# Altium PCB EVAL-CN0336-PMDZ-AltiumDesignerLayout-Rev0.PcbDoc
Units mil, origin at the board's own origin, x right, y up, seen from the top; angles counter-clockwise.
Board outline 2055 x 800 mil, 2 copper layers (Top Layer, Bottom Layer); 30 components, 22 nets, 95 pads, 26 vias.
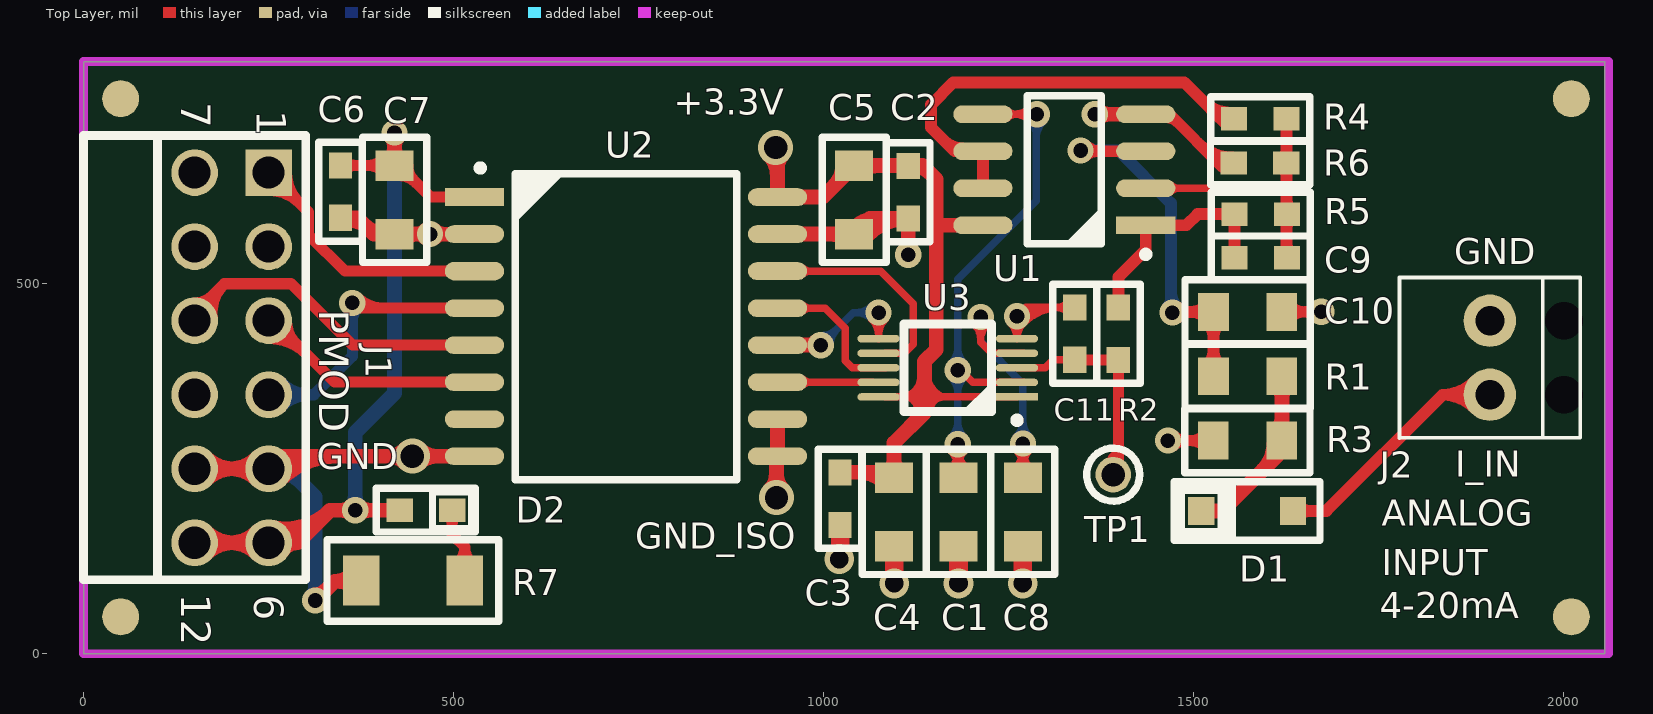
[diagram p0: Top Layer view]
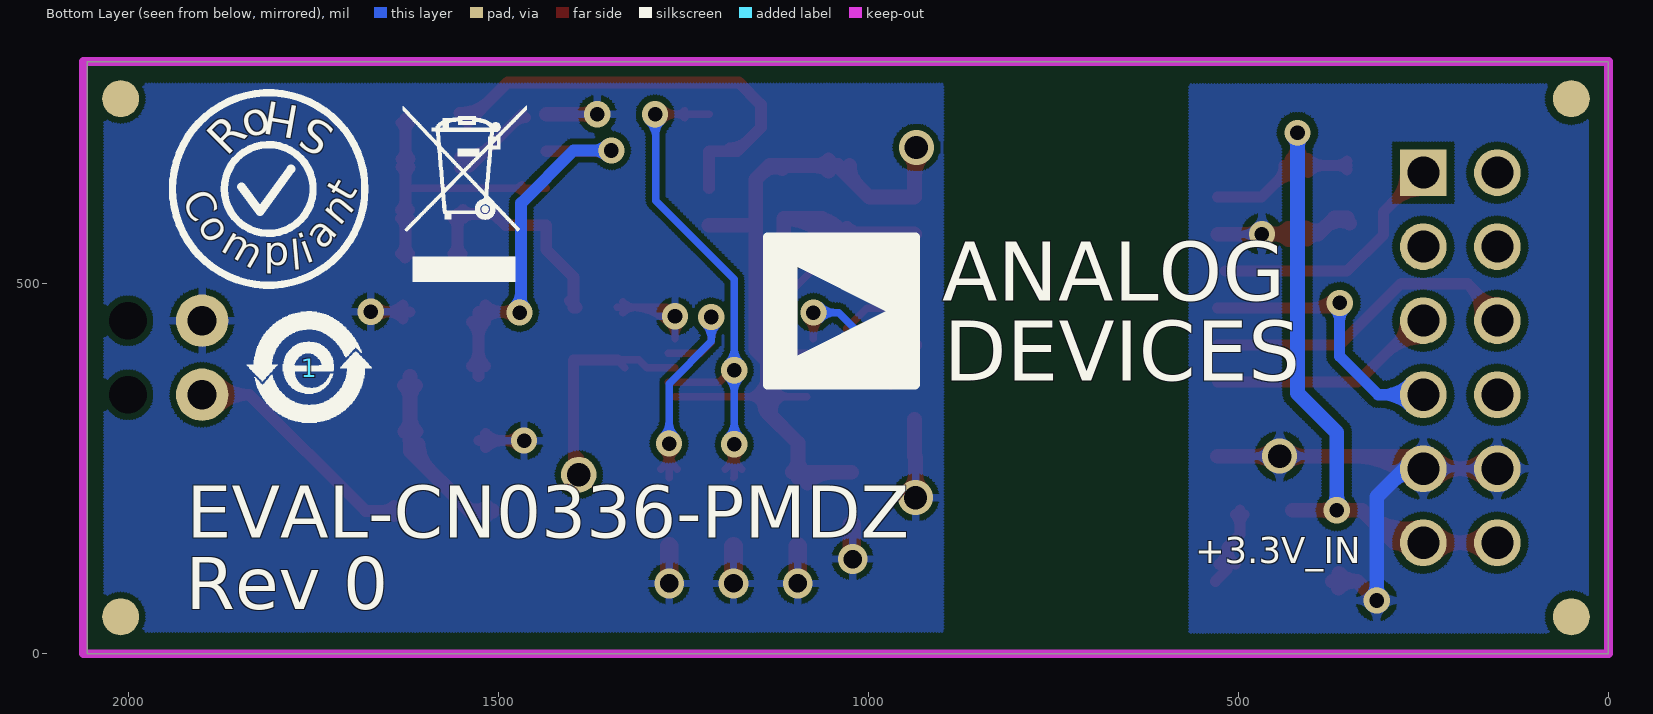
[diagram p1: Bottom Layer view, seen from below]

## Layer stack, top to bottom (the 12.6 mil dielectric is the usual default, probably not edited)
Top Layer: signal copper 1.4
Dielectric: dielectric 12.6, FR-4, Dk 4.8
Bottom Layer: signal copper 1.4

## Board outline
0,0 2055,0 2055,800 0,800

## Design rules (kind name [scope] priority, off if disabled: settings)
Clearance [All] p1: gap=8
ComponentClearance [All] p1 off: gap=10 collisioncheckmode=3 verticalgap=10 showdistances=FALSE
PolygonConnect [All] p1: connectstyle=Relief reliefconductorwidth=10 reliefentries=4 polygonreliefangle="90 Angle"
RoutingVias [All] p1: holewidth=19.68 width=35.43 viastyle="Through Hole" minholewidth=19.68 minwidth=35.43 maxholewidth=39.37 maxwidth=78.74
SilkscreenOverComponentPads [All] p1: minsilkscreentomaskgap=10
SolderMaskExpansion [All] p1: expansion=4
Width [All] p1: maxlimit=60 minlimit=10 preferedwidth=10
26 further rules are at their usual default settings.

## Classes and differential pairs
component class CN0336: C1 C2 C3 C4 C5 C6 C7 C8 C9 C10 C11 D1 D2 J1 J2 R1 R2 R3 R4 R5 R6 R7 U1 U2 U3

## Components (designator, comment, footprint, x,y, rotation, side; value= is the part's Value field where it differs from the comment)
1 "Comment" "Sign E" 1755,386 r180 bottom
C1 "" "0805 AD" 1182,238 r270 top
C2 "" "0603 AD" 1114,588 r90 top
C3 "" "0603 AD" 1022,245 r270 top
C4 "" "0805 AD" 1095,238 r270 top
C5 "Cap" "0805 AD" 1041,567 r90 top
C6 "" "0603 AD" 347,589 r90 top
C7 "Cap" "0805 AD" 420,567 r90 top
C8 "" "0805 AD" 1269,238 r270 top (schematic designator C12)
C9 "" "0603 AD" 1555,535 r0 top
C10 "" "0805 AD" 1619,462 r180 top
C11 "" "0603 AD" 1339,468 r270 top (schematic designator C9)
D1 "" SOD123 1572,193 r180 top
D2 "LED3" "0603 Diode" 427,194 r0 top (schematic designator D1)
J1 "PMOD CON 12 Pin" "PMOD 12 Pin" 200,400 r270 top locked
J2 "CON 2" "Phoenix Klema pitch 2_54" 1900,350 r90 top
R1 "RESISTOR" "0805 AD" 1619,375 r180 top
R2 "RESISTOR" "0603 AD" 1398,397.08 r90 top (schematic designator R3)
R3 "RESISTOR" "0805 AD" 1526,288 r0 top
R4 "RESISTOR" "0603 AD" 1625,723 r180 top
R5 "RESISTOR" "0603 AD" 1555,594 r0 top
R6 "RESISTOR" "0603 AD" 1554,663 r0 top
R7 "RESISTOR" "1206 AD" 375,99 r0 top
TP1 "Comment" TestPoint 1391,242 r0 top
U1 "AD8606" SOICN_8 1435,579 r180 top
U2 "ADuM5401" SOICW_16 528,617 r0 top
U3 "AD7091R" MSOP10 1261,347 r90 top
? "Comment" "ROHS COMPLIANT" 1810,628 r180 bottom
? "Comment" "Analog Devices" 1136,363 r180 bottom
? "Comment" "No Trash" 1547,610 r180 bottom

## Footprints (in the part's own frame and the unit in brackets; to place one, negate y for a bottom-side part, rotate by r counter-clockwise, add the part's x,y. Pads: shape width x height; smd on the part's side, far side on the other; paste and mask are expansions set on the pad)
"0603 AD" [mm]
  rect 0.9x0.8 smd: 1(0,0) 2(1.8,0)
  silkscreen extent -0.8,-0.75 2.6,0.75
"0603 Diode" [mm]
  rect 0.9x0.8 smd: A(0,0) K(1.8,0)
  silkscreen extent -0.8,-0.75 2.6,0.76
"0805 AD" [mm]
  rect 1.05x1.3 smd: 1(0,0) 2(2.35,0)
  silkscreen extent -0.98,-1.1 3.32,1.1
"1206 AD" [mm]
  rect 1.25x1.7 smd: 1(0,0) 2(3.55,0)
  silkscreen extent -1.17,-1.4 4.72,1.4
"Analog Devices" [mil]
  silkscreen extent -1,0 201,201
MSOP10 [mm]
  rect 0.254x1.45 smd: 1(0,0)
  oval 0.254x1.45 smd: 2(0.5,0) 3(1,0) 4(1.5,0) 5(2,0) 6(2,4.75) 7(1.5,4.75) 8(1,4.75) 9(0.5,4.75) 10(0,4.75)
  silkscreen extent -0.88,-0.08 2.5,3.87
"No Trash" [mil]
  silkscreen extent -82,-107 86,130
"Phoenix Klema pitch 2_54" [mm]
  round 1.8 hole 1: 1(0,0) 2(2.54,0)
  round 0 hole 1.3: ""(0,-2.54) ""(2.54,-2.54)
  silkscreen extent -1.48,-3.1 4.02,3.1
"PMOD 12 Pin" [mm]
  rect 1.6x1.6 hole 1.1: 1(-6.35,1.27)
  round 1.6 hole 1.1: 2(-3.81,1.27) 3(-1.27,1.27) 4(1.27,1.27) 5(3.81,1.27) 6(6.35,1.27) 7(-6.35,-1.27) 8(-3.81,-1.27) 9(-1.27,-1.27) 10(1.27,-1.27) 11(3.81,-1.27) 12(6.35,-1.27)
  silkscreen extent -7.62,-5.08 7.62,2.54
"ROHS COMPLIANT" [mil]
  silkscreen extent -130,-130 130,130
"Sign E" [mil]
  silkscreen extent -85,-74 84,76
SOD123 [mm]
  rect 0.9x0.95 smd: A(-1.575,0) K(1.575,0)
  silkscreen extent -2.5,-1 2.5,1
SOICN_8 [mil]
  rect 80x24 smd: 1(0,0)
  oval 80x24 smd: 2(0,-50) 3(0,-100) 4(0,-150) 5(220,-150) 6(220,-100) 7(220,-50) 8(220,0)
  silkscreen extent -3,-175 160,43
SOICW_16 [mil]
  rect 80x24 smd: 1(0,0)
  oval 80x24 smd: 2(0,-50) 4(0,-150) 5(0,-200) 6(0,-250) 7(0,-300) 8(0,-350) 9(409.45,-350) 10(409.45,-300) 11(409.45,-250) 12(409.45,-200) 13(409.45,-150) 14(409.45,-100) 15(409.45,-50) 16(409.45,0)
  oval 80x25 smd: 3(0,-100)
  silkscreen extent 5,-382 354,43
TestPoint [mil]
  round 48 hole 32: 1(0,0)
  silkscreen extent -36,-36 36,36

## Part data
C1 C2 C3 C4 C6 C8 C9 C10 C11: library part Cap, "Capacitor"
C5 C7: "Capacitor"
D1: library part Diode, "Diode"
D2: "LED"
J1: "PMOD CONNECTOR 12 PIN"
J2: "Input Connector"
R1 R2 R3 R4 R5 R6 R7: "Resistor"
U1: "Dual Operational Amplifier"
U2: "Quad Digital Isolator with integrated DC/DC converter"
U3: "ADC"

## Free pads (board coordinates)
  round 50 all layers, no hole paste+15 mask+15: ""(50,50) ""(50,750) ""(2010,50) ""(2010,750)

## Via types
v1: diameter 35.43, hole 19.68, Top Layer to Bottom Layer, tented both sides, 18 vias
v2: diameter 40, hole 25, Top Layer to Bottom Layer, tented both sides, 4 vias
v3: diameter 47.24, hole 31.5, Top Layer to Bottom Layer, 3 vias
v4: diameter 35, hole 20, Top Layer to Bottom Layer, 1 vias

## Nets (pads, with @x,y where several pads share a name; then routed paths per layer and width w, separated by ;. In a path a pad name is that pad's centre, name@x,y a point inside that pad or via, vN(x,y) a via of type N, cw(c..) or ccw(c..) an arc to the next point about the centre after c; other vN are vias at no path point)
+3.3V: C2.2 C3.1 C4.1 C5.2 U1.8 U2.16 U3.1 U3.10 | length 1472.6
  Top Layer w10: C3.1@1021,244 C3.1 ; U3.10@1082.99,347 1136,347 U3.1 ; C4.1 C4.1@1102,245 ; 1107,347 ccw(c1103,375) 1131,379 ; 1111.14,347.72 cw(c1107.5,328.5) 1127,327 ; C2.2@1113.35,659.52 C2.2 ; 1130.29,320.29 ccw(c1132.29,332) 1144,330 cw(c1161.5,329.5) 1162,347 ; 1142.21,401.21 ccw(c1178.21,383) 1160,347
  Top Layer w19.68: C3.1 1088,245 C4.1 ; 1047.04,245 cw(c1047.04,194.96) C4.1@1082.42,230.34
  Top Layer w20: v3@925.37,674.37 cw(c896.2,645.2) 937.45,645.2 ; 937.45,657.03 cw(c961.97,657.03) v3@944.63,674.37 ; v3@937.45,681.55 U2.16 998.48,617 C5.2 1113.35,659.52 1133.48,659.52 1152,641 1152,579 ; 1014.39,632.91 ccw(c987.77,659.52) C5.2@1025.41,659.52 ; C5.2@1053.47,651.98 cw(c1071.68,633.76) 1071.68,659.52 cw(c1071.68,685.28) C5.2@1053.47,667.06 ; C4.1@1087.46,245.54 ccw(c1069.24,263.76) 1095,263.76 ccw(c1120.76,263.76) C4.1@1102.54,245.54 ; C4.1 1095,285 1136,326 1136,347 1136,395 1152,411 1152,579 ; C2.2@1116.25,655.54 cw(c1125.62,633.5) 1142.56,650.44 ; U1.8 1152,579
  other v3: 935,684
+3.3V_IN: C6.2 C7.2 D2.A J1.6 J1.12 U2.1 | length 1740.3
  Top Layer w15: C6.2@352.83,654.03 cw(c366.91,639.95) 366.91,659.87 cw(c366.91,679.78) C6.2@352.83,665.7 ; C6.2@353,659.87 420,659.87 425.65,659.87 468.52,617 U2.1 ; 382.45,659.87 cw(c382.45,626.89) C7.2@405.77,650.21 ; 384.12,659.87 ccw(c384.12,690.48) C7.2@405.77,668.83 ; C7.2@424.92,646.35 cw(c424.92,611.95) 449.24,636.28 ; C7.2@438.09,659.52 ccw(c467.28,659.52) 446.64,638.88
  Top Layer w20: J1.12 J1.6 289,150 ; J1.12@165.2,134.8 cw(c201.9,98.1) 201.9,150 cw(c201.9,201.9) J1.12@165.2,165.2 ; J1.6@234.8,134.8 ccw(c198.1,98.1) 198.1,150 ccw(c198.1,201.9) J1.6@234.8,165.2 ; J1.6@250.32,151.46 ccw(c263.48,211.76) 307.12,168.12 ; J1.6@254.58,171 ccw(c272.75,254.25) 333,194 ; J1.6@268.18,138.52 cw(c289,125.37) 289,150 ; J1.6@268.18,161.48 ccw(c289,174.63) 289,150 ; v1@361.54,188.54 ccw(c348.37,175.37) 348.37,194 ccw(c348.37,212.63) v1@361.54,199.46 ; v1@372.46,188.54 cw(c385.63,175.37) 385.63,194 cw(c385.63,212.63) v1@372.46,199.46 ; C7.2@412.46,667.06 ccw(c394.24,685.28) 420,685.28 ccw(c445.76,685.28) C7.2@427.54,667.06 ; v4@414.7,698.7 cw(c401.89,685.89) 420,685.89 cw(c438.11,685.89) v4@425.3,698.7 ; C7.2 420,659.87 v4(420,704) ; D2.A v1(367,194) 333,194 ; 289,150 333,194
  Bottom Layer w20: v1@361.54,199.46 ccw(c348.37,212.63) 367,212.63 ccw(c385.63,212.63) v1@372.46,199.46 ; v1(367,194) 367,299 420,352 v4(420,704) ; v4@414.7,698.7 cw(c401.89,685.89) 420,685.89 cw(c438.11,685.89) v4@425.3,698.7
GND: C6.1 C7.1 J1.5 J1.11 R7.1 U2.2 U2.8 | length 1619.7
  Top Layer w19.68: v1(313,72) 339,98 ; v1@313,79.87 ccw(c313,98.88) 326.44,85.44 ccw(c339.88,72) v1@320.87,72 ; 341.77,98 cw(c341.77,65.77) R7.1@364.56,88.56 ; C6.1@349.67,581.76 cw(c362.45,556.49) 382.48,576.52 ; C6.1@353,589 370,589 392,567 ; R7.1@364.15,109.01 cw(c339,132.22) 339,98 ; R7.1@373,98 339,98 ; 381.54,577.46 ccw(c396.09,592.01) C7.1@408.53,575.62 ; C7.1@406.75,560.08 ccw(c392,547.82) 392,567 ; C7.1@406.75,573.92 cw(c392,586.18) 392,567 ; C7.1@432.58,559.34 cw(c451.06,540.86) 451.06,567 cw(c451.06,593.14) C7.1@432.58,574.66 ; v1@462.43,561.43 ccw(c448.99,547.99) 448.99,567 ccw(c448.99,586.01) v1@462.43,572.57 ; v1@473.57,561.43 cw(c487.01,547.99) 487.01,567 cw(c487.01,586.01) v1@473.57,572.57 ; U2.2 392,567
  Top Layer w20: J1.11 J1.5 267,267 U2.8 ; J1.11@165.2,234.8 cw(c201.9,198.1) 201.9,250 cw(c201.9,301.9) J1.11@165.2,265.2 ; J1.5@234.8,234.8 ccw(c198.1,198.1) 198.1,250 ccw(c198.1,301.9) J1.5@234.8,265.2 ; J1.5@251.06,248.94 cw(c294.65,205.35) 294.65,267 ; J1.5@265.2,234.8 cw(c342.94,157.06) 342.94,267 ; v3@434.37,257.37 ccw(c411.11,234.11) 411.11,267 ccw(c411.11,299.89) v3@434.37,276.63 ; v3@453.63,257.37 cw(c476.89,234.11) 476.89,267 cw(c476.89,299.89) v3@453.63,276.63
  Bottom Layer w20: J1.5 275,250 313,212 v1(313,72) ; J1.5@250.06,248.51 cw(c252.55,190.88) 293.33,231.67 ; v1@307.54,77.46 ccw(c294.37,90.63) 313,90.63 ccw(c331.63,90.63) v1@318.46,77.46
  other v1: 468,567
  other v3: 444,267
GND_ISO: C1.2 C2.1 C3.2 C4.2 C5.1 C8.2 C10.1 C11.1 J2.2 R3.1 R6.1 U1.4 U2.9 U2.10 U2.15 U3.5 | length 1659.4
  Top Layer w10: v1@1252.1,446.92 cw(c1231.36,425.74) U3.5 ; v1@1262.92,454.08 cw(c1296.53,420.47) 1296.53,468 ; v1@1269.9,446.92 ccw(c1290.64,425.74) U3.5 ; v1@1269.99,447.01 cw(c1320.67,396.33) 1320.67,468 ; v1@1270,462 v1(1261,456) ; C11.1@1331.4,460.4 ccw(c1313.05,442.05) 1313.05,468 ccw(c1313.05,493.95) C11.1@1331.4,475.6 ; C11.1 1273,468 v1(1261,456) ; U3.5 v1(1261,456)
  Top Layer w15: U1.4@1463,724.5 cw(c1463,703.98) 1477.51,718.49 ; U1.4@1467,729 R6.1@1538,658 ; v1@1472.22,280.78 cw(c1489.66,263.34) 1489.66,288 cw(c1489.66,312.66) v1@1472.22,295.22 ; v1@1478,288 R3.1 ; 1505.46,690.54 ccw(c1552.03,737.11) R6.1@1552.03,671.25 ; R3.1@1516.69,278.69 ccw(c1494.21,256.21) 1494.21,288 ccw(c1494.21,319.79) R3.1@1516.69,297.31 ; 1531.07,664.93 ccw(c1552.03,685.89) R6.1@1552.03,656.25 ; C10.1 v1(1672,462) ; C10.1@1628.31,452.69 cw(c1650.79,430.21) 1650.79,462 cw(c1650.79,493.79) C10.1@1628.31,471.31 ; v1@1664.78,454.78 ccw(c1647.34,437.34) 1647.34,462 ccw(c1647.34,486.66) v1@1664.78,469.22
  Top Layer w20: v3@926.37,220.63 ccw(c903.11,243.89) 936,243.89 ccw(c968.89,243.89) v3@945.63,220.63 ; v3(936,211) 936,265.55 U2.9 U2.10 ; U2.15 C5.1 1062,588 ; C5.1@1028.53,559.46 ccw(c1010.32,541.24) 1010.32,567 ccw(c1010.32,592.76) C5.1@1028.53,574.54 ; C5.1@1038.78,573.01 cw(c1071,545.88) 1071,588 ; C5.1@1054.08,560.13 cw(c1114,509.67) C2.1 ; C5.1@1056.37,569.17 cw(c1076.63,573.37) 1062,588 ; v1@1108.54,544.46 ccw(c1095.37,557.63) 1114,557.63 ccw(c1132.63,557.63) v1@1119.46,544.46 ; v1(1114,539) C2.1 ; v1(1366,729) U1.4 ; v1@1371.46,723.54 cw(c1384.63,710.37) 1384.63,729 cw(c1384.63,747.63) v1@1371.46,734.46 ; 1062,588 C2.1
  Top Layer w25: v2(1021,128) 1021,131 1022,132 C3.2 ; v2(1095,95) C4.2 ; v2(1182,95) C1.2 ; v2(1269,95) C8.2
  other v1: 1465,288
NetC1_1: C1.1 U1.5 U3.2 | length 1081.4
  Top Layer w10: C1.1@1170.92,249.08 ccw(c1146.59,273.41) v1@1181,273.41 ; v1@1172.01,274.01 cw(c1150.3,252.3) 1181,252.3 cw(c1211.7,252.3) v1@1189.99,274.01 ; v1@1181,278.24 ccw(c1222.24,278.24) C1.1@1193.08,249.08 ; v1(1181,283) 1181,239 C1.1 ; v1@1185,383 1201.31,366.69 U3.2 U3.2@1270,366.69 ; U1.5 v1(1288,729) ; U1.5@1247.95,724.05 cw(c1259.9,712.1) 1259.9,729 cw(c1259.9,745.9) U1.5@1247.95,733.95 ; v1@1279.01,720.01 ccw(c1257.3,698.3) 1257.3,729 ccw(c1257.3,759.7) v1@1279.01,737.99
  Bottom Layer w10: v1@1172.01,291.99 ccw(c1150.3,313.7) 1181,313.7 ccw(c1211.7,313.7) v1@1189.99,291.99 ; v1@1172.01,374.01 cw(c1150.3,352.3) 1181,352.3 cw(c1211.7,352.3) v1@1189.99,374.01 ; v1@1172.01,391.99 ccw(c1150.3,413.7) 1181,413.7 ccw(c1211.7,413.7) v1@1189.99,391.99 ; v1@1181,289 v1(1181,283) v1(1181,383) 1181,506 1287,612 v1@1287,729 ; v1@1279.01,720.01 cw(c1259.71,700.71) 1287,700.71 ; 1287,695.89 cw(c1321.11,695.89) v1@1296.99,720.01
NetC9_1: C9.1 R2.2 R5.1 U1.1 | length 395.5
  Top Layer w16: R2.2@1394,467.95 R2.2@1403,476.95 ; R2.2 1398,509 1435,546 U1.1 1490,579 1505,594 R5.1@1538,594 ; R5.1@1547.55,588.52 ccw(c1534.33,575.29) 1534.33,594 ccw(c1534.33,612.71) R5.1@1547.55,599.48 ; C9.1@1549.52,540.48 ccw(c1536.29,553.71) 1555,553.71 ccw(c1573.71,553.71) C9.1@1560.48,540.48 ; R5.1@1549.52,588.52 cw(c1536.29,575.29) 1555,575.29 cw(c1573.71,575.29) R5.1@1560.48,588.52 ; C9.1 R5.1
NetC9_2: C9.2 R4.1 R5.2 R6.2 U1.2 | length 581.6
  Top Layer w10: U1.2 1624,629 1625,630 ; U1.2@1467.95,624.05 cw(c1479.9,612.1) 1479.9,629 cw(c1479.9,645.9) U1.2@1467.95,633.95
  Top Layer w16: R6.2@1619.39,657.52 cw(c1605.84,643.97) 1625,643.97 ; R6.2@1619.39,668.48 ccw(c1605.84,682.03) 1625,682.03 ; R4.1@1619.52,717.52 cw(c1606.29,704.29) 1625,704.29 cw(c1643.71,704.29) R4.1@1630.48,717.52 ; C9.2@1620.39,540.48 ccw(c1609.25,551.61) 1625,551.61 ; R5.2@1620.39,588.52 cw(c1609.25,577.39) 1625,577.39 ; R5.2@1620.39,599.48 ccw(c1609.25,610.61) 1625,610.61 ; 1625,555.8 ccw(c1646.66,555.8) C9.2@1631.34,540.48 ; 1625,573.2 cw(c1646.66,573.2) R5.2@1631.34,588.52 ; 1625,614.8 ccw(c1646.66,614.8) R5.2@1631.34,599.48 ; 1625,644.62 cw(c1643.25,644.62) R6.2@1630.34,657.52 ; 1625,681.38 ccw(c1643.25,681.38) R6.2@1630.34,668.48 ; R4.1 1625,630 1625,535.87 C9.2
NetC10_2: C10.2 R1.2 U1.3 | length 829
  Top Layer w16: v1@1347,679 U1.3 ; v1@1353.87,673.13 cw(c1368.04,658.96) 1368.04,679 ; v1@1353.87,686.87 ccw(c1372.87,705.87) 1372.87,679 ; v1@1472,462 C10.2 R1.2 ; v1@1477.87,454.13 cw(c1496.87,435.13) 1496.87,462 ; v1@1477.87,467.87 ccw(c1492.04,482.04) 1492.04,462 ; R1.2@1517.52,388.88 ccw(c1495.89,410.51) 1526.48,410.51 ccw(c1557.07,410.51) R1.2@1535.44,388.88 ; C10.2@1517.52,448.12 cw(c1495.89,426.49) 1526.48,426.49 cw(c1557.07,426.49) C10.2@1535.44,448.12 ; C10.2@1517.52,453.04 ccw(c1495.89,431.41) 1495.89,462 ccw(c1495.89,492.59) C10.2@1517.52,470.96
  Bottom Layer w16: v1@1353.87,673.13 cw(c1370.46,656.54) 1370.46,680 cw(c1370.46,703.46) v1@1353.87,686.87 ; v1@1355.57,680 v1(1347,680) 1398,680 1469,609 v1@1469,461 ; v1@1464.13,467.87 ccw(c1452.37,479.63) 1469,479.63 ; 1469,489.29 ccw(c1499.29,489.29) v1@1477.87,467.87
  other v1: 1471,461
NetC12_1: C8.1 U3.4 | length 640
  Top Layer w10: v1@1203.01,446.01 cw(c1181.3,424.3) 1212,424.3 cw(c1242.7,424.3) v1@1220.99,446.01 ; v1(1212,455) 1212,421 1226.94,406.06 U3.4 U3.4@1270,406.06 ; C8.1@1257.92,249.08 ccw(c1231.17,275.83) 1269,275.83 ccw(c1306.83,275.83) C8.1@1280.08,249.08 ; v1@1260.01,275.01 cw(c1238.3,253.3) 1269,253.3 cw(c1299.7,253.3) v1@1277.99,275.01 ; C8.1@1263.88,252.81 ccw(c1261.39,260) 1269,260 ; v1(1269,284) C8.1 1269,260 ; C8.1@1274.12,252.81 cw(c1276.61,260) 1269,260
  Bottom Layer w10: v1@1203.01,446.01 cw(c1181.3,424.3) 1212,424.3 cw(c1242.7,424.3) v1@1220.99,446.01 ; v1(1212,455) 1212,422 1269,365 1269,338 ; v1@1260.01,292.99 ccw(c1238.3,314.7) 1269,314.7 ccw(c1299.7,314.7) v1@1277.99,292.99 ; v1(1269,284) 1269,338 ; 1269,346 1269,338
NetD1_A: D1.A J2.1 | length 469.6
  Top Layer w16: D1.A@1631.01,193 1679,193 1836,350 ; D1.A@1640.88,186.13 cw(c1657.47,169.54) 1657.47,193 cw(c1657.47,216.46) D1.A@1640.88,199.87 ; J2.1@1880.13,331.08 ccw(c1836,289.07) 1836,350 ; J2.1@1880.13,368.92 cw(c1836,410.93) 1836,350 ; J2.1 1836,350
NetD1_K: D1.K R1.1 R3.2 | length 395.1
  Top Layer w20: D1.K@1506.99,193 D1.K 1538,193 1618.52,273.52 R3.2 1619,288.48 R1.1 ; D1.K@1515.45,187.54 cw(c1528.62,174.37) 1528.62,193 cw(c1528.62,211.63) D1.K@1515.45,198.46 ; 1593.55,248.55 ccw(c1559.01,283.08) R3.2@1607.85,283.08 ; R3.2@1610.98,300.47 ccw(c1591.6,319.84) 1619,319.84 ; R1.1@1611.46,362.53 cw(c1593.24,344.32) 1619,344.32 cw(c1644.76,344.32) R1.1@1626.54,362.53 ; 1619,317.52 ccw(c1643.12,317.52) R3.2@1626.06,300.47
NetD2_K: D2.K R7.2 | length 193.3
  Top Layer w15: D2.K@492.03,188.17 cw(c477.95,174.09) 497.87,174.09 cw(c517.78,174.09) D2.K@503.7,188.17 ; D2.K 497.87,161.13 515,144 ; R7.2@504.06,121.2 ccw(c485.78,144) 515,144 ; R7.2@525.75,120.97 cw(c545.04,144) 515,144 ; R7.2@530.76,98 515,113.76 515,144
NetU2_11: U2.11 U3.9 | length 155.2
  Top Layer w10: U2.11 937.76,366.69 U3.9@1065.99,366.69 ; U2.11@970.4,362.05 cw(c981.59,350.86) 981.59,366.69 ; U2.11@970.4,371.95 ccw(c983.11,384.66) 983.11,366.69
NetU2_12: U2.12 U3.6 | length 364
  Top Layer w10: v1@1065.01,452.01 cw(c1043.32,430.32) 1073.99,430.32 cw(c1104.72,430.28) v1@1082.99,452.01 ; U3.6 v1(1074,461)
  Top Layer w20: U2.12 v1(996,417) ; v1@990.54,411.54 ccw(c977.37,398.37) 977.37,417 ccw(c977.37,435.63) v1@990.54,422.46
  Bottom Layer w10: v1(996,417) 1040,461 v1(1074,461) ; v1@996,429.72 ccw(c996,460.42) 1017.71,438.71 ccw(c1039.42,417) v1@1008.72,417 ; v1@1065.01,452.01 ccw(c1043.3,430.3) 1043.3,461 ccw(c1043.3,491.7) v1@1065.01,469.99
NetU2_13: U2.13 U3.8 | length 249.6
  Top Layer w10: U2.13 1002,467 1029,440 1029,396 1038.63,386.37 U3.8@1065.99,386.37 ; U2.13@970.4,462.05 cw(c982.35,450.1) 982.35,467 cw(c982.35,483.9) U2.13@970.4,471.95 ; U3.8@1047.63,386.37 U3.8@1065.99,386.37 ; U3.8@1082.99,386.37 U3.8@1065.99,386.37
NetU2_14: U2.14 U3.7 | length 326.3
  Top Layer w10: U2.14 1077,517 1121,473 1121,418 1109.06,406.06 U3.7@1082.99,406.06 ; U2.14@970.4,512.05 cw(c982.35,500.1) 982.35,517 cw(c982.35,533.9) U2.14@970.4,521.95
PMOD_CONVST: J1.9 U2.5 | length 546.7
  Top Layer w15: J1.9 150,460 190,500 ; J1.9@150,474 ccw(c150,507.79) 173.89,483.89 ; J1.9@158.93,451.1 cw(c191.43,455.12) 168.27,478.27 ; J1.9@173.81,452.94 cw(c230.1,459.9) 190,500 ; U2.5 363,417 280,500 190,500
PMOD_MISO: J1.3 U2.6 | length 440.4
  Top Layer w15: J1.3@250,426 cw(c250,353.59) 301.21,404.79 ; J1.3@250,441 cw(c250,404.8) 275.6,430.4 ; J1.3 256,450 339,367 U2.6 ; J1.3@274,450 ccw(c317.44,450) 286.72,419.28
  Bottom Layer w12: J1.3 J1.3@254.67,445.33
  Bottom Layer w15: J1.3 J1.3@252,450
PMOD_SCK: J1.4 U2.4 | length 542.3
  Top Layer w15: v1(363,474) 370,467 U2.4 ; v1@370.22,481.22 ccw(c404.56,515.56) 404.56,467
  Bottom Layer w15: J1.4 311,350 363,402 v1(363,474) ; J1.4@266.97,333.03 cw(c307.93,292.07) 307.93,350 cw(c307.93,407.93) J1.4@266.97,366.97 ; v1@355.78,466.78 cw(c338.34,449.34) 363,449.34 cw(c387.66,449.34) v1@370.22,466.78
PMOD_SS: J1.1 U2.3 | length 432.2
  Top Layer w15: J1.1@250,626 cw(c250,565.66) 292.67,608.33 ; J1.1 251,650 304,597 304,566 353,517 U2.3@518,517 ; J1.1@274,650 ccw(c329.51,650) 290.26,610.74
TP1: C11.2 R2.1 TP1.1 U3.3 | length 351.5
  Top Layer w10: U3.3 1299.37,386.37 1310.13,397.13 C11.2 ; C11.2@1329.15,386.37 C11.2@1338.47,395.69
  Top Layer w15: C11.2 1397.94,397.13 R2.1 1398,279 ; 1398,279 1398,258.9 cw(c1374.1,258.9) TP1.1 1391,264 1398,271 1398,279
VREF: R4.2 U1.6 U1.7 | length 720.2
  Top Layer w16: 1163.1,692.9 ccw(c1187,716.8) U1.6@1187,683 ; U1.7 U1.6 1177,679 1145,711 1145,742 1175,772 1487,772 1509,750 ; 1511.34,747.66 ccw(c1552.17,788.48) R4.2@1552.17,730.75 ; 1535.13,723.87 1509,750 ; R4.2@1538.13,728.87 1535.13,728.87 cw(c1535.13,719.15) R4.2@1544.61,721.29 ; R4.2@1541.16,717.84 1509,750
pads on no net: J1.2 J1.7 J1.8 J1.10 J2. U2.7

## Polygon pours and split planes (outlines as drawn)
GND on Bottom Layer "GND_BOT" (hatched 90Degree grid 0 track 4, pour order 1001): 566,547 566,769 27.95,769 27.95,601 27.95,29 27,28 27.95,29 126.04,29 566,29 566,281
GND_ISO on Bottom Layer "GND_ISO_BOT" (hatched 90Degree grid 0 track 4, pour order 1000): 899,417 899,770 2032,770 2032,30 1729.06,30 899,30

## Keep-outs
Keep-Out Layer:
  lines w12: 0,0 0,800 2060,800 2060,0 0,0

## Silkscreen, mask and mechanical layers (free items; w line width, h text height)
Top Overlay:
  text "+3.3V" at 797,728 h35
  text "GND" at 1852,526 h35
  text "PMOD" at 318,465 h40 r270
  text "GND" at 315,249 h35
  text "I_IN" at 1853,239 h35
  text "ANALOG" at 1754,173 h35
  text "GND_ISO" at 745,142 h35
  text "INPUT" at 1754,106 h35
  text "4-20mA" at 1751,48 h35
Bottom Overlay:
  text "EVAL-CN0336-PMDZ" at 1921,134 h120
  text "+3.3V_IN" at 558,122 h35
  text "Rev 0" at 1922,37 h120
Mechanical 1:
  lines w12: 30,30 2030,30 2030,770 30,770 30,30

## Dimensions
0,800 to 0,0 on Mechanical 1
0,800 to 2060,800 on Mechanical 1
